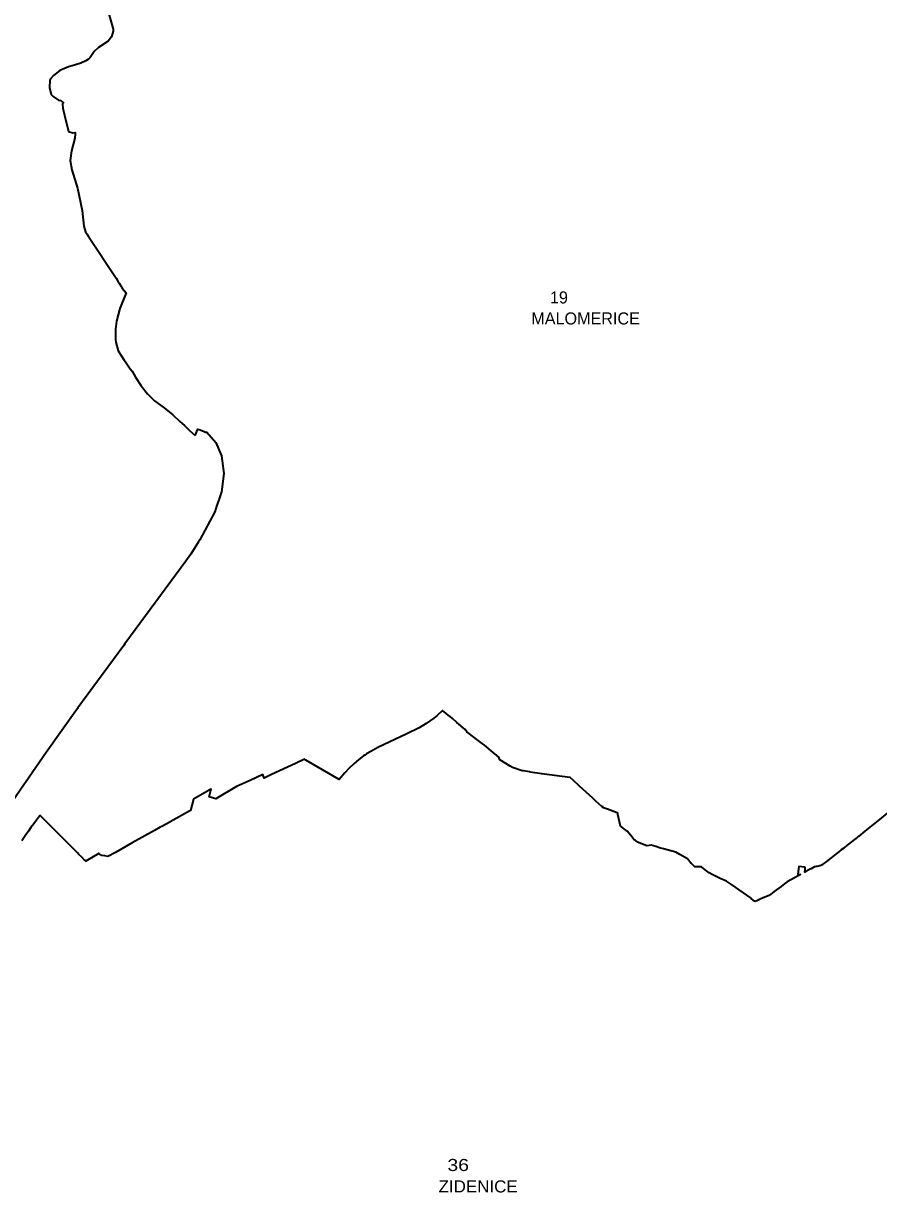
# Model space of a CAD drawing. Extents: x -610940 to -588976, y -1170376 to -1149800.
# Drawn here: x -595838 to -594068, y -1160183 to -1157762 of the extents above; entities that cross this region are included whole.
import ezdxf

# ---------------------------------------------------------------- set-up
doc = ezdxf.new("R2010")
doc.units = 0
doc.header["$LTSCALE"] = 10
doc.layers.add('54', color=7, linetype='Continuous', lineweight=35)
doc.layers.add('55', color=7, linetype='Continuous')
doc.layers.add('56', color=7, linetype='Continuous')

msp = doc.modelspace()

# ---------------------------------------------------------------- linework, layer by layer
at = {"layer": '54'}
for p, q in [((-595646.16, -1158289.45), (-595642.29, -1158295.83)), ((-595642.29, -1158295.83), (-595639.64, -1158300.19)), ((-595639.64, -1158300.19), (-595636.56, -1158305.28)), ((-595636.56, -1158305.28), (-595633.5, -1158310.34)), ((-595726.32, -1159181.02), (-595790.68, -1159271.79))]:
    msp.add_line(p, q, dxfattribs=at)
for points in [[(-595668.51, -1157714.33), (-595663.78, -1157727.69), (-595660.49, -1157744.84), (-595652.35, -1157773.96), (-595652.13, -1157778.23), (-595655.88, -1157789.62), (-595662.83, -1157798.94), (-595682.66, -1157812.17), (-595691.38, -1157820.17), (-595700.01, -1157832.84), (-595703.09, -1157836.25), (-595708.63, -1157839.88), (-595719.19, -1157844.48), (-595732.1, -1157848.66), (-595744.93, -1157851.7), (-595762.37, -1157859.95), (-595775.67, -1157870.03), (-595781.94, -1157876.76), (-595783.11, -1157879.36), (-595784.26, -1157894.5)], [(-595784.26, -1157894.5), (-595780.45, -1157909.63), (-595776.6, -1157913.59), (-595765.46, -1157920.75), (-595760.32, -1157922.07), (-595758.59, -1157923.52), (-595758.18, -1157923.78), (-595754.88, -1157926.26), (-595756.84, -1157929.08)], [(-595756.84, -1157929.08), (-595757.09, -1157929.36), (-595756.13, -1157937.92), (-595752.72, -1157952.37), (-595744.85, -1157985.69)], [(-595744.85, -1157985.69), (-595735.97, -1157988.98), (-595735.46, -1157988.94), (-595730.74, -1157987.85), (-595730.65, -1157990.52), (-595731.7, -1157999.59), (-595738.22, -1158026.12), (-595741.35, -1158046.14), (-595738.05, -1158065.6), (-595725.76, -1158103.56), (-595716.09, -1158149.77), (-595712.72, -1158181.96), (-595709.46, -1158193.62), (-595706.75, -1158197.72)], [(-595706.75, -1158197.72), (-595702.93, -1158203.51), (-595646.16, -1158289.45)], [(-595633.5, -1158310.34), (-595625.34, -1158320.14), (-595638.25, -1158352.34), (-595645.47, -1158378.73), (-595647.61, -1158395.02), (-595647.56, -1158416.8), (-595646.66, -1158422.46), (-595641.77, -1158440.13), (-595629.65, -1158459.35), (-595626.63, -1158462.95), (-595616.79, -1158477.32), (-595612.97, -1158481.94), (-595605.73, -1158494.71), (-595594.36, -1158512.36), (-595580.94, -1158529.34), (-595566.73, -1158543.9)], [(-595566.73, -1158543.9), (-595546.33, -1158558.27), (-595529.04, -1158572.73), (-595514.52, -1158586.52), (-595504.67, -1158594.85), (-595494.91, -1158604.13), (-595494.12, -1158604.88), (-595482.31, -1158615.47)], [(-595482.31, -1158615.47), (-595476.7, -1158602.03), (-595472.48, -1158603.79), (-595463.98, -1158607.22), (-595458.93, -1158609.31), (-595458.66, -1158608.68), (-595439.75, -1158630.2), (-595428.23, -1158657.91), (-595423.16, -1158694.14), (-595427.81, -1158732.26), (-595432.99, -1158746.82), (-595433.12, -1158747.13), (-595433.73, -1158748.92), (-595437, -1158758.07), (-595437.51, -1158759.65)], [(-595437.51, -1158759.65), (-595437.63, -1158760.04), (-595441.81, -1158773.47), (-595472.93, -1158831.46), (-595475.5, -1158835.94), (-595491.81, -1158861.18), (-595501.7, -1158875.86), (-595627.73, -1159047.17)], [(-595627.73, -1159047.17), (-595629.99, -1159050.21), (-595639.49, -1159063.29), (-595641.69, -1159066.21), (-595641.86, -1159066.41), (-595725.34, -1159179.74), (-595726.32, -1159181.02)], [(-594706.71, -1159323.61), (-594706.9, -1159323.58), (-594764.8, -1159316.3), (-594765, -1159316.27), (-594789.44, -1159312.31), (-594790.79, -1159312.09), (-594803.27, -1159310.07), (-594805.53, -1159309.57), (-594825.47, -1159302.92), (-594825.73, -1159302.79), (-594830.79, -1159300.27), (-594851.8, -1159287.3), (-594851.85, -1159287.16), (-594853.72, -1159281.57), (-594853.95, -1159281.38), (-594869.81, -1159268.2), (-594884.23, -1159256.2), (-594884.48, -1159256.01), (-594888.38, -1159253.06), (-594902.09, -1159242.7), (-594903.02, -1159242), (-594920.26, -1159228.96), (-594923.72, -1159224.57), (-594940.65, -1159209.69), (-594949.95, -1159201.52), (-594954.97, -1159197.44), (-594955.34, -1159197.14), (-594970.29, -1159184.99), (-594981.56, -1159195.33), (-594988.48, -1159200.83), (-595004.17, -1159211.63), (-595019.04, -1159220.6), (-595044.2, -1159233.45), (-595104.42, -1159261.78), (-595119.2, -1159269.67), (-595127.82, -1159274.68), (-595131.6, -1159277.4), (-595133.97, -1159279.12), (-595140.25, -1159283.67), (-595148.47, -1159290.56)], [(-595790.68, -1159271.79), (-595833.93, -1159333.96), (-595835.97, -1159336.96)], [(-595148.47, -1159290.56), (-595149.02, -1159291.03), (-595153.66, -1159294.92), (-595153.8, -1159295.06), (-595163.96, -1159304.65), (-595172.48, -1159313.75), (-595184.28, -1159327.71), (-595253.63, -1159287.51), (-595256.29, -1159285.55), (-595275.09, -1159294.38), (-595324.19, -1159317.51), (-595339.72, -1159325.4), (-595342.79, -1159317.7), (-595368.37, -1159329.59), (-595397.14, -1159342.34), (-595439.51, -1159367.61), (-595453.38, -1159363.8), (-595453.86, -1159363.67), (-595450.26, -1159350.19), (-595449.58, -1159347.73), (-595452.52, -1159349.4), (-595453.19, -1159349.78), (-595458.07, -1159352.55), (-595485.8, -1159368.31), (-595486.3, -1159370.07), (-595486.69, -1159371.51), (-595492.1, -1159392.16), (-595533.92, -1159415.63), (-595534.74, -1159416.06), (-595551.27, -1159424.87), (-595555.27, -1159426.74), (-595566.79, -1159433.43), (-595612.56, -1159458.75), (-595647.7, -1159479.24), (-595663.38, -1159487.01), (-595669.67, -1159485.98), (-595675.97, -1159485.28), (-595679.09, -1159483.76), (-595680.23, -1159482.67), (-595681.47, -1159480.97)], [(-595835.97, -1159336.96), (-595844.74, -1159349.78), (-595894.52, -1159421.49), (-595894.82, -1159421.93), (-595897.57, -1159425.99), (-595898.38, -1159427.21), (-595910.24, -1159444.37), (-595912.08, -1159446.96)], [(-594462.73, -1159492.75), (-594463.34, -1159491.93), (-594479.44, -1159482.87), (-594487.79, -1159478.17), (-594505.76, -1159473.37), (-594513.24, -1159471.37), (-594521.2, -1159469.08), (-594529.13, -1159466.8), (-594538.41, -1159463.85), (-594547.15, -1159465.41), (-594548, -1159465.11), (-594556.9, -1159461.94), (-594558.12, -1159461.34), (-594563.5, -1159458.71), (-594566.13, -1159457.42), (-594571.04, -1159454.37), (-594573.95, -1159452.56), (-594581.05, -1159443.6), (-594588.29, -1159434.74), (-594591.16, -1159432.58), (-594600.13, -1159425.83), (-594601.94, -1159424.47), (-594607.95, -1159400.58), (-594607.53, -1159397.69), (-594608.7, -1159397.25), (-594609.45, -1159396.97), (-594629.44, -1159389.44), (-594639.34, -1159385.71), (-594639.05, -1159384.7), (-594640.97, -1159383.65), (-594646.87, -1159378.24), (-594653.24, -1159372.41), (-594659.76, -1159366.44), (-594666.58, -1159360.2), (-594673.25, -1159354.08), (-594680.19, -1159347.72), (-594686.87, -1159341.61), (-594700.07, -1159329.52), (-594706.49, -1159323.63), (-594706.71, -1159323.61)], [(-593997.18, -1159354.17), (-594069.29, -1159413.18), (-594079.13, -1159421.23), (-594096.59, -1159435.07), (-594109.8, -1159445.55), (-594110.32, -1159445.95), (-594111.07, -1159446.55), (-594111.55, -1159446.93), (-594115.2, -1159449.83), (-594118.02, -1159452.06), (-594123.97, -1159456.74), (-594132.97, -1159463.81), (-594133.47, -1159464.2), (-594137.3, -1159467.21), (-594140.12, -1159469.69), (-594145.23, -1159473.48), (-594150.38, -1159477.5), (-594152.8, -1159479.4), (-594175.63, -1159497.34), (-594183.18, -1159502.87), (-594186.34, -1159505.17), (-594187.34, -1159505.91), (-594189.98, -1159506.42), (-594192.7, -1159507.37), (-594195.14, -1159507.85), (-594195.24, -1159507.87), (-594197.12, -1159508.14), (-594200.74, -1159508.67), (-594207.36, -1159512.49), (-594207.71, -1159512.7), (-594208.41, -1159513.1), (-594215.12, -1159516.11), (-594215.74, -1159516.49), (-594218.52, -1159518.44)], [(-595681.47, -1159480.97), (-595681.88, -1159481.21), (-595708.79, -1159497.2), (-595709.59, -1159496.39), (-595710.72, -1159495.25), (-595716.93, -1159489), (-595722.93, -1159482.96), (-595725.87, -1159480), (-595729.28, -1159476.56), (-595732.7, -1159473.13), (-595735.63, -1159470.17), (-595739.08, -1159466.71), (-595744.2, -1159461.55), (-595745.15, -1159460.59), (-595748.87, -1159456.84), (-595768.24, -1159437.6), (-595771.17, -1159434.68), (-595803.61, -1159402.44), (-595803.79, -1159402.68), (-595804.77, -1159404), (-595810.91, -1159412.31), (-595816.55, -1159419.94), (-595822.58, -1159427.25), (-595827.68, -1159434.79), (-595832.82, -1159442.37), (-595837.14, -1159448.75), (-595841.21, -1159454.77)], [(-594218.52, -1159518.44), (-594220.87, -1159519.79), (-594220.22, -1159513.8), (-594220.12, -1159512.89), (-594220, -1159511.81), (-594219.78, -1159509.76), (-594220.78, -1159509.65), (-594233.22, -1159508.22), (-594234.99, -1159524.12), (-594229.5, -1159524.73), (-594236.04, -1159528.35), (-594240.83, -1159531.01), (-594257.24, -1159539.8), (-594261.8, -1159543.12), (-594269.54, -1159549.12), (-594284.17, -1159559.87), (-594291.58, -1159565.71), (-594293.46, -1159567.18), (-594308.58, -1159573.7), (-594311.48, -1159575.03), (-594317.49, -1159577.79), (-594320.14, -1159579), (-594323.59, -1159580.59), (-594324.62, -1159579.77), (-594327.46, -1159577.49), (-594331.8, -1159574.01), (-594332.03, -1159573.85), (-594372.29, -1159545.33), (-594382.84, -1159538.38), (-594395.8, -1159532.59), (-594403.99, -1159528.62), (-594412.39, -1159524.55), (-594418.56, -1159521.07), (-594426.92, -1159515.23), (-594434.36, -1159508.76), (-594434.76, -1159508.77), (-594448.56, -1159508.96), (-594455.51, -1159501.98), (-594456.56, -1159500.93), (-594462.73, -1159492.75)]]:
    msp.add_lwpolyline(points, dxfattribs=at)

# ---------------------------------------------------------------- texts
at = {"layer": '55'}
msp.add_text('MALOMERICE ', height=25, dxfattribs=at).set_placement((-594786.83, -1158385.61))
at = {"layer": '55', "width": 1.05}
msp.add_text('ZIDENICE ', height=25, dxfattribs=at).set_placement((-594978.74, -1160182.96))
at = {"layer": '56'}
msp.add_text('19 ', height=25, dxfattribs=at).set_placement((-594748.19, -1158342.05))
at = {"layer": '56', "width": 1.2}
msp.add_text('36 ', height=25, dxfattribs=at).set_placement((-594960.48, -1160138.61))

doc.saveas('drawing.dxf')
